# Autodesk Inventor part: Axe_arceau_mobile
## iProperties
Created: 2011-01
Part Number: Axe_arceau_mobile
Document SubType Name: Modeling
Designer: eric
Density: 1 g/cm^3
Mass: 16.0917 g
Surface Area: 98.5297 cm^2
Volume: 16.0917 cm^3
Author: eric
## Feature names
1. Base1
